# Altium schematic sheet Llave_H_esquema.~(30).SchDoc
size A4
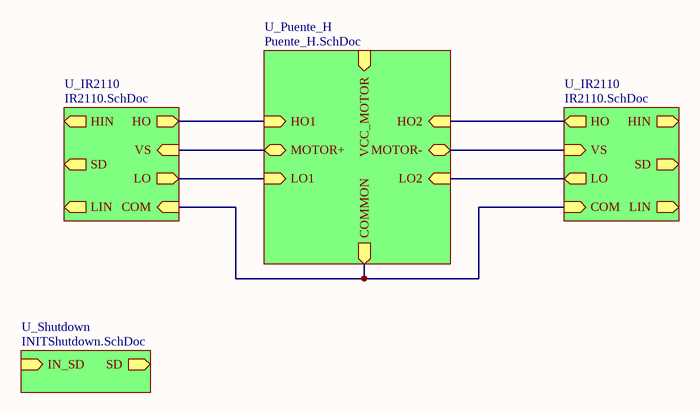
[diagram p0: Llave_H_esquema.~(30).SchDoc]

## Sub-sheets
U_IR2110 = IR2110.SchDoc: SD (out), HIN (out), LIN (out), HO (out), LO (out), VS (in), COM (in)
U_IR2110 = IR2110.SchDoc: SD (out), HIN (out), LIN (out), HO (out), LO (out), VS (in), COM (in)
U_Puente_H = Puente_H.SchDoc: HO1 (in), LO1 (in), HO2 (in), LO2 (in), MOTOR+ (bidir), MOTOR- (bidir), VCC_MOTOR (in), COMMON (out)
U_Shutdown = INITShutdown.SchDoc: IN_SD (in), SD (out)

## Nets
(unnamed): sheet U_IR2110/HO, sheet U_Puente_H/HO1
(unnamed): sheet U_IR2110/LO, sheet U_Puente_H/LO1  [a separate net that carries the same name]
(unnamed): sheet U_IR2110/VS, sheet U_Puente_H/MOTOR+  [a separate net that carries the same name]
(unnamed): sheet U_IR2110/COM, sheet U_IR2110/COM, sheet U_Puente_H/COMMON  [a separate net that carries the same name]
(unnamed): sheet U_IR2110/HO, sheet U_Puente_H/HO2  [a separate net that carries the same name]
(unnamed): sheet U_IR2110/LO, sheet U_Puente_H/LO2  [a separate net that carries the same name]
(unnamed): sheet U_IR2110/VS, sheet U_Puente_H/MOTOR-  [a separate net that carries the same name]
